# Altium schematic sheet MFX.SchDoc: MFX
size A4; DocumentNumber: MB1167; Revision: B.1; SheetNumber: 16; SheetTotal: 17; Project: STM327x6G-EVAL
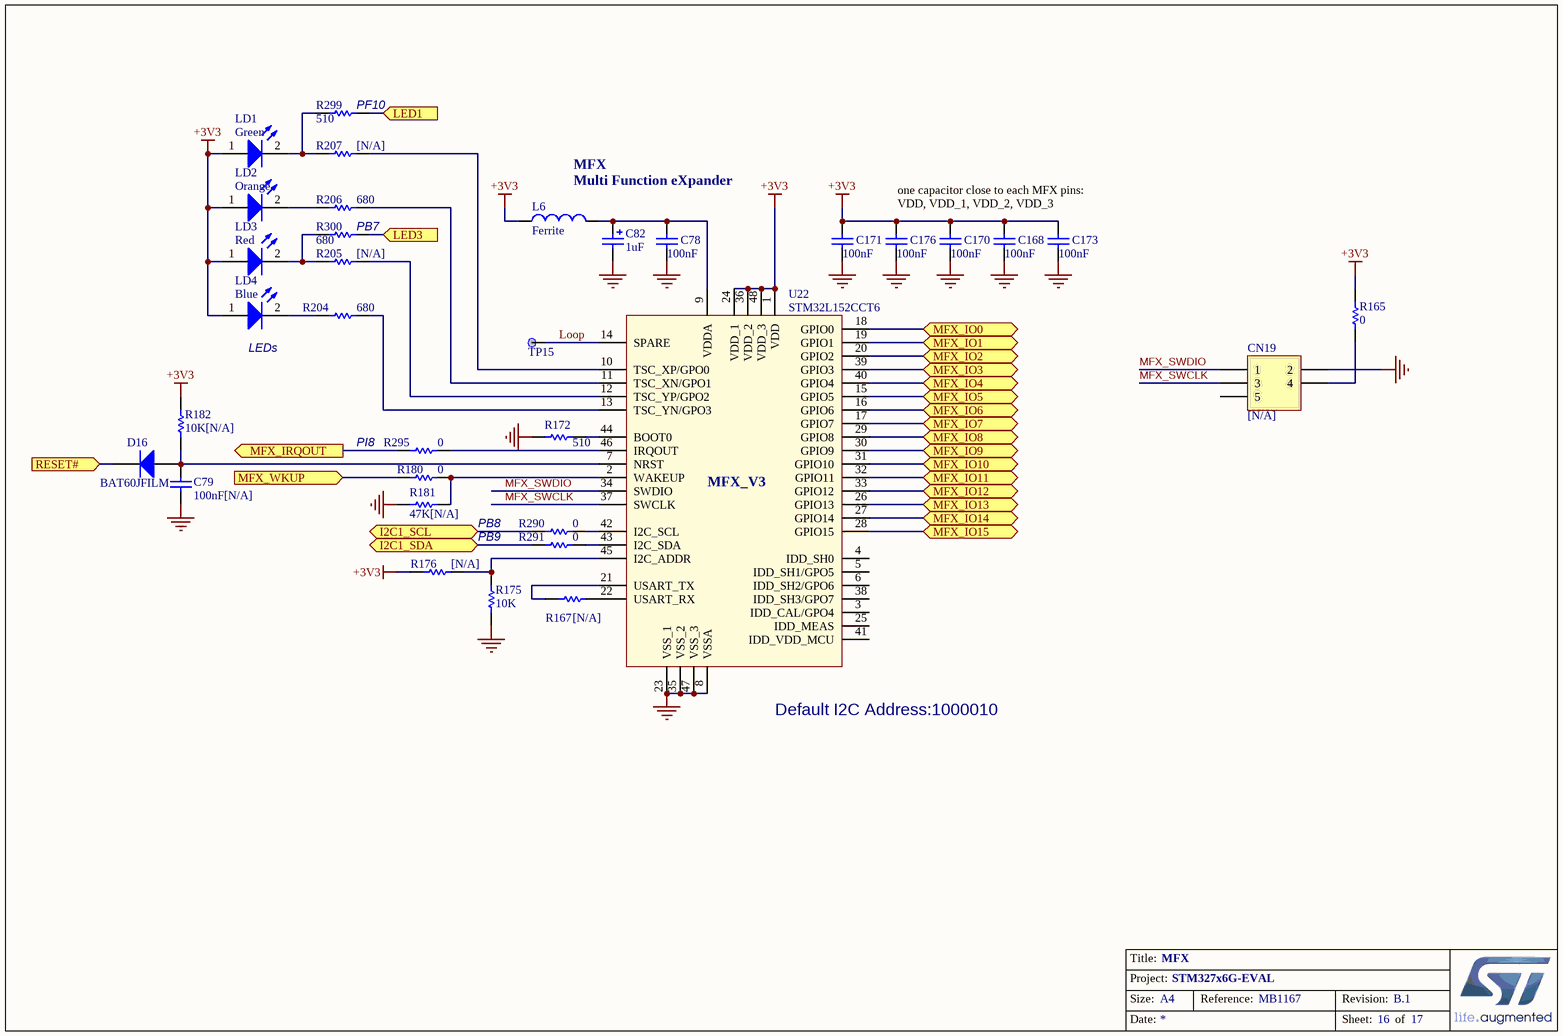
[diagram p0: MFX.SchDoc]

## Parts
C78  100nF  [0402C]
C79  100nF[N/A]  [0402C]
C82  1uF  [TAN-A]
C168  100nF  [0402C]
C170  100nF  [0402C]
C171  100nF  [0402C]
C173  100nF  [0402C]
C176  100nF  [0402C]
CN19  [N/A]  [HDR_2X3-1_2R54-6]
D16  BAT60JFILM  [SOD-323]
L6  Ferrite  [0603L]
LD1  Green  [0603D]
LD2  Orange  [0603D]
LD3  Red  [0603D]
LD4  Blue  [0603D]
R165  0  [0603R]
R167  [N/A]  [0603R]
R172  510  [0402R]
R175  10K  [0402R]
R176  [N/A]  [0603R]
R180  0  [0603R]
R181  47K[N/A]  [0402R]
R182  10K[N/A]  [0402R]
R204  680  [0603R]
R205  [N/A]  [0603R]
R206  680  [0603R]
R207  [N/A]  [0603R]
R290  0  [0603R]
R291  0  [0603R]
R295  0  [0603R]
R299  510  [0603R]
R300  680  [0603R]
TP15  (no value)  [TP]
U22  STM32L152CCT6  [LQFP48_0R5_9X9]

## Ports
I2C1_SCL (bidir), I2C1_SDA (bidir), LED1 (in), LED3 (in), MFX_IO0 (bidir), MFX_IO1 (bidir), MFX_IO2 (bidir), MFX_IO3 (bidir), MFX_IO4 (bidir), MFX_IO5 (bidir), MFX_IO6 (bidir), MFX_IO7 (bidir), MFX_IO8 (bidir), MFX_IO9 (bidir), MFX_IO10 (bidir), MFX_IO11 (bidir), MFX_IO12 (bidir), MFX_IO13 (bidir), MFX_IO14 (bidir), MFX_IO15 (bidir), MFX_IRQOUT (out), MFX_WKUP (in), RESET# (in)

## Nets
+3V3: C168.2 C170.1 C171.2 C173.2 C176.2 L6.1 LD1.1(A) LD2.1(A) LD3.1(A) LD4.1(A) R165.1 R176.2 R182.2 U22.1(VDD) U22.24(VDD_1) U22.36(VDD_2) U22.48(VDD_3)
GND: C78.1 C79.1 C82.2 C168.1 C170.2 C171.1 C173.1 C176.1 CN19.2 R172.2 R175.2 R181.1 U22.8(VSSA) U22.23(VSS_1) U22.35(VSS_2) U22.47(VSS_3)
I2C1_SCL: R290.1 ; port I2C1_SCL
I2C1_SDA: R291.1 ; port I2C1_SDA
LED1: R299.1 ; port LED1
LED3: R300.1 ; port LED3
Loop: TP15.1 U22.14(SPARE)
MFX_IO0: U22.18(GPIO0) ; port MFX_IO0
MFX_IO1: U22.19(GPIO1) ; port MFX_IO1
MFX_IO2: U22.20(GPIO2) ; port MFX_IO2
MFX_IO3: U22.39(GPIO3) ; port MFX_IO3
MFX_IO4: U22.40(GPIO4) ; port MFX_IO4
MFX_IO5: U22.15(GPIO5) ; port MFX_IO5
MFX_IO6: U22.16(GPIO6) ; port MFX_IO6
MFX_IO7: U22.17(GPIO7) ; port MFX_IO7
MFX_IO8: U22.29(GPIO8) ; port MFX_IO8
MFX_IO9: U22.30(GPIO9) ; port MFX_IO9
MFX_IO10: U22.31(GPIO10) ; port MFX_IO10
MFX_IO11: U22.32(GPIO11) ; port MFX_IO11
MFX_IO12: U22.33(GPIO12) ; port MFX_IO12
MFX_IO13: U22.26(GPIO13) ; port MFX_IO13
MFX_IO14: U22.27(GPIO14) ; port MFX_IO14
MFX_IO15: U22.28(GPIO15) ; port MFX_IO15
MFX_IRQOUT: R295.1 ; port MFX_IRQOUT
MFX_SWCLK: CN19.3 U22.37(SWCLK)
MFX_SWDIO: CN19.1 U22.34(SWDIO)
MFX_WKUP: R180.2 ; port MFX_WKUP
RESET#: D16.2(K) ; port RESET#
NetC78_2: C78.2 C82.1 L6.2 U22.9(VDDA)
NetC79_2: C79.2 D16.1(A) R182.1 U22.7(NRST)
NetCN19_4: CN19.4 R165.2
NetLD1_2: LD1.2(K) R207.2 R299.2
NetLD2_2: LD2.2(K) R206.2
NetLD3_2: LD3.2(K) R205.2 R300.2
NetLD4_2: LD4.2(K) R204.2
NetR167_1: R167.1 U22.21(USART_TX)
NetR167_2: R167.2 U22.22(USART_RX)
NetR172_1: R172.1 U22.44(BOOT0)
NetR175_1: R175.1 R176.1 U22.45(I2C_ADDR)
NetR180_1: R180.1 R181.2 U22.2(WAKEUP)
NetR204_1: R204.1 U22.13(TSC_YN/GPO3)
NetR205_1: R205.1 U22.12(TSC_YP/GPO2)
NetR206_1: R206.1 U22.11(TSC_XN/GPO1)
NetR207_1: R207.1 U22.10(TSC_XP/GPO0)
NetR290_2: R290.2 U22.42(I2C_SCL)
NetR291_2: R291.2 U22.43(I2C_SDA)
NetR295_2: R295.2 U22.46(IRQOUT)

Not connected (* = marked no-connect by the designer): CN19 5; U22 3(IDD_CAL/GPO4) 4(IDD_SH0) 5(IDD_SH1/GPO5) 6(IDD_SH2/GPO6) 25(IDD_MEAS) 38(IDD_SH3/GPO7) 41(IDD_VDD_MCU)

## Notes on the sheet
- (near R299) PF10
- (near R300) PB7
- MFX
  Multi Function eXpander
- one capacitor close to each MFX pins: VDD, VDD_1, VDD_2, VDD_3
- (near LD4) LEDs
- PI8
- PB8
- PB9
- (near U22) Default I2C Address:1000010

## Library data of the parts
C78 C79 C168 C170 C171 C173 C176 = Cap_100nF_X7R_10%_0402: Capacitor,100nF,16V,X7R,10%,0402,YAGEO; Manuf_Part_1: CC0402KRX7R7BB104
C82 = Cap_1uF_POL_10%_TANA: Polarized Capacitor,1uF,16V,10%,typeA,AVX; Manuf_Part_1: TAJA105K016R
CN19 = Header 3X2: Header, 3-Pin, Dual row
D16 = Diode: Default Diode; Code - JEDEC: DO-214-AB
L6 = BEAD_600R_350MA_0603: Bead,600R,350mA,0603,FCM1608KF-601T03,Tai-tech; Manuf_2: TDK; Manuf_Part_2: MPZ1608S300A; Value: 100uH; Comment_1: bead,30R,5A,0603,MPZ1608S300A,TDK
LD1-LD4 = LED2: Typical RED, GREEN, YELLOW, AMBER GaAs LED
R165 R290 R291 R295 = Res1: Resistor; Value: 1K; Ordered by: Subcon
R167 = res1: Resistor; Value: 1K; Ordered by: Subcon
R172 R181 R182 = Resistor_ST: Resistor 0402 / 0603 / 0805; Description: Resistor 0402 or 0603 or 0805; Value: 10K
R175 = Resistor_ST: Resistor 0402 / 0603 / 0805; Description: Resistor 0402 or 0603 or 0805
R176 R180 R204-R207 R299 R300 = Res1: Resistor; Value: 1K
TP15 = TP
U22 = MFX: Multifunction expander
